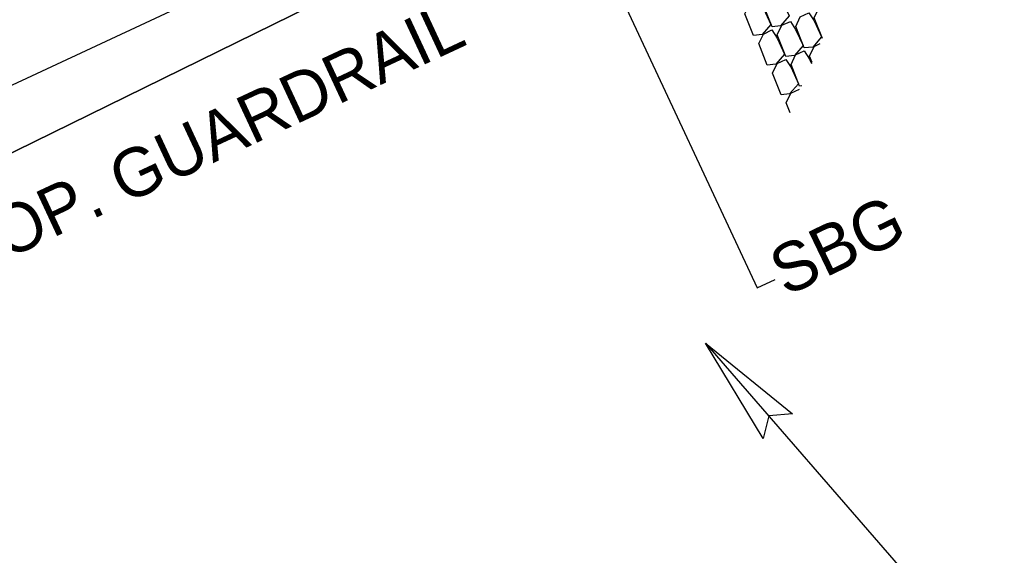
# Model space of a CAD drawing. Extents: x 2320644 to 2322941, y 921672 to 923041.
# Drawn here: x 2321522 to 2321644, y 922058.5 to 922124.4 of the extents above; entities that cross this region are included whole.
import ezdxf

# ---------------------------------------------------------------- set-up
doc = ezdxf.new("R2010")
doc.units = 0
for name, color, linetype in [('Prop Approach Slab', 7, 'Continuous'), ('Prop Conc Shoulder Berm Gutter', 7, 'Continuous'), ('Prop Guardrail', 7, 'Continuous'), ('Prop North Arrow NAD83 for Plan Sheets CELL', 7, 'Continuous'), ('Sheet Profile Grid Major CELL', 7, 'Continuous'), ('Sheet Profile Grid Minor CELL', 7, 'Continuous'), ('Sheet Sticker Exception Certification CELL', 7, 'Continuous')]:
    doc.layers.add(name, color=color, linetype=linetype)

msp = doc.modelspace()

# ---------------------------------------------------------------- linework, layer by layer
at = {"layer": 'Prop Approach Slab'}
msp.add_line((2321416.2, 922067.48), (2321809.47, 922250.79), dxfattribs=at)
at = {"layer": 'Prop Conc Shoulder Berm Gutter'}
msp.add_line((2321579.9, 922136.91), (2321500.59, 922097.99), dxfattribs=at)
at = {"layer": 'Prop Guardrail'}
msp.add_line((2321500.59, 922097.99), (2321590.38, 922142.05), dxfattribs=at)
at = {"layer": 'Prop North Arrow NAD83 for Plan Sheets CELL'}
msp.add_line((2321606.54, 922084.56), (2321669.93, 922011.69), dxfattribs=at)
at = {"layer": 'Sheet Profile Grid Major CELL'}
for points in [[(2321615.3, 922127.85), (2321615.94, 922126.85), (2321616.86, 922124.88), (2321615.78, 922123.63), (2321614.73, 922123.52), (2321613.67, 922126.17), (2321614.23, 922127.35), (2321615.3, 922127.85)], [(2321613.02, 922126.79), (2321613.67, 922125.79), (2321614.58, 922123.82), (2321613.5, 922122.57), (2321612.45, 922122.45), (2321611.39, 922125.11), (2321611.96, 922126.29), (2321613.02, 922126.79)], [(2321620.94, 922122.09), (2321619.92, 922124.64), (2321620.49, 922125.83), (2321621.55, 922126.32)], [(2321617, 922124.2), (2321617.64, 922123.21), (2321618.56, 922121.23), (2321617.48, 922119.98), (2321616.43, 922119.87), (2321615.37, 922122.52), (2321615.93, 922123.71), (2321617, 922124.2)], [(2321619.28, 922125.26), (2321619.92, 922124.27), (2321620.84, 922122.3), (2321619.75, 922121.04), (2321618.7, 922120.93), (2321617.65, 922123.58), (2321618.21, 922124.77), (2321619.28, 922125.26)], [(2321619.28, 922125.26), (2321619.92, 922124.27), (2321620.84, 922122.3), (2321619.75, 922121.04), (2321618.7, 922120.93), (2321617.65, 922123.58), (2321618.21, 922124.77), (2321619.28, 922125.26)], [(2321614.72, 922123.14), (2321615.37, 922122.14), (2321616.28, 922120.17), (2321615.2, 922118.92), (2321614.15, 922118.81), (2321613.09, 922121.46), (2321613.66, 922122.64), (2321614.72, 922123.14)], [(2321618.41, 922116.25), (2321618.13, 922116.22), (2321617.07, 922118.87), (2321617.63, 922120.06), (2321618.7, 922120.55)], [(2321618.7, 922120.55), (2321619.34, 922119.56), (2321619.6, 922119)], [(2321619.66, 922119.14), (2321619.35, 922119.93), (2321619.91, 922121.12), (2321620.68, 922121.47)], [(2321616.42, 922119.49), (2321617.07, 922118.5), (2321617.99, 922116.52), (2321616.9, 922115.27), (2321615.85, 922115.16), (2321614.79, 922117.81), (2321615.36, 922119), (2321616.42, 922119.49)], [(2321616.98, 922112.94), (2321616.49, 922114.16), (2321617.06, 922115.35), (2321618.12, 922115.84)]]:
    msp.add_lwpolyline(points, dxfattribs=at)
at = {"layer": 'Sheet Profile Grid Minor CELL'}
for p, q in [((2321589.31, 922141.92), (2321612.89, 922091.38)), ((2321612.89, 922091.38), (2321615.13, 922092.42))]:
    msp.add_line(p, q, dxfattribs=at)
at = {"layer": 'Sheet Sticker Exception Certification CELL'}
msp.add_lwpolyline([(2321613.65, 922072.85), (2321606.54, 922084.56), (2321617.26, 922075.89), (2321614.32, 922075.62)], close=True, dxfattribs=at)

# ---------------------------------------------------------------- texts
at = {"layer": 'Prop North Arrow NAD83 for Plan Sheets CELL'}
msp.add_text('PROP. GUARDRAIL', height=6, rotation=24.9913, dxfattribs=at).set_placement((2321510.28, 922090.15))
at = {"layer": 'Sheet Profile Grid Minor CELL'}
msp.add_text('SBG', height=6, rotation=25.7165, dxfattribs=at).set_placement((2321616.43, 922090.28))

doc.saveas('drawing.dxf')
